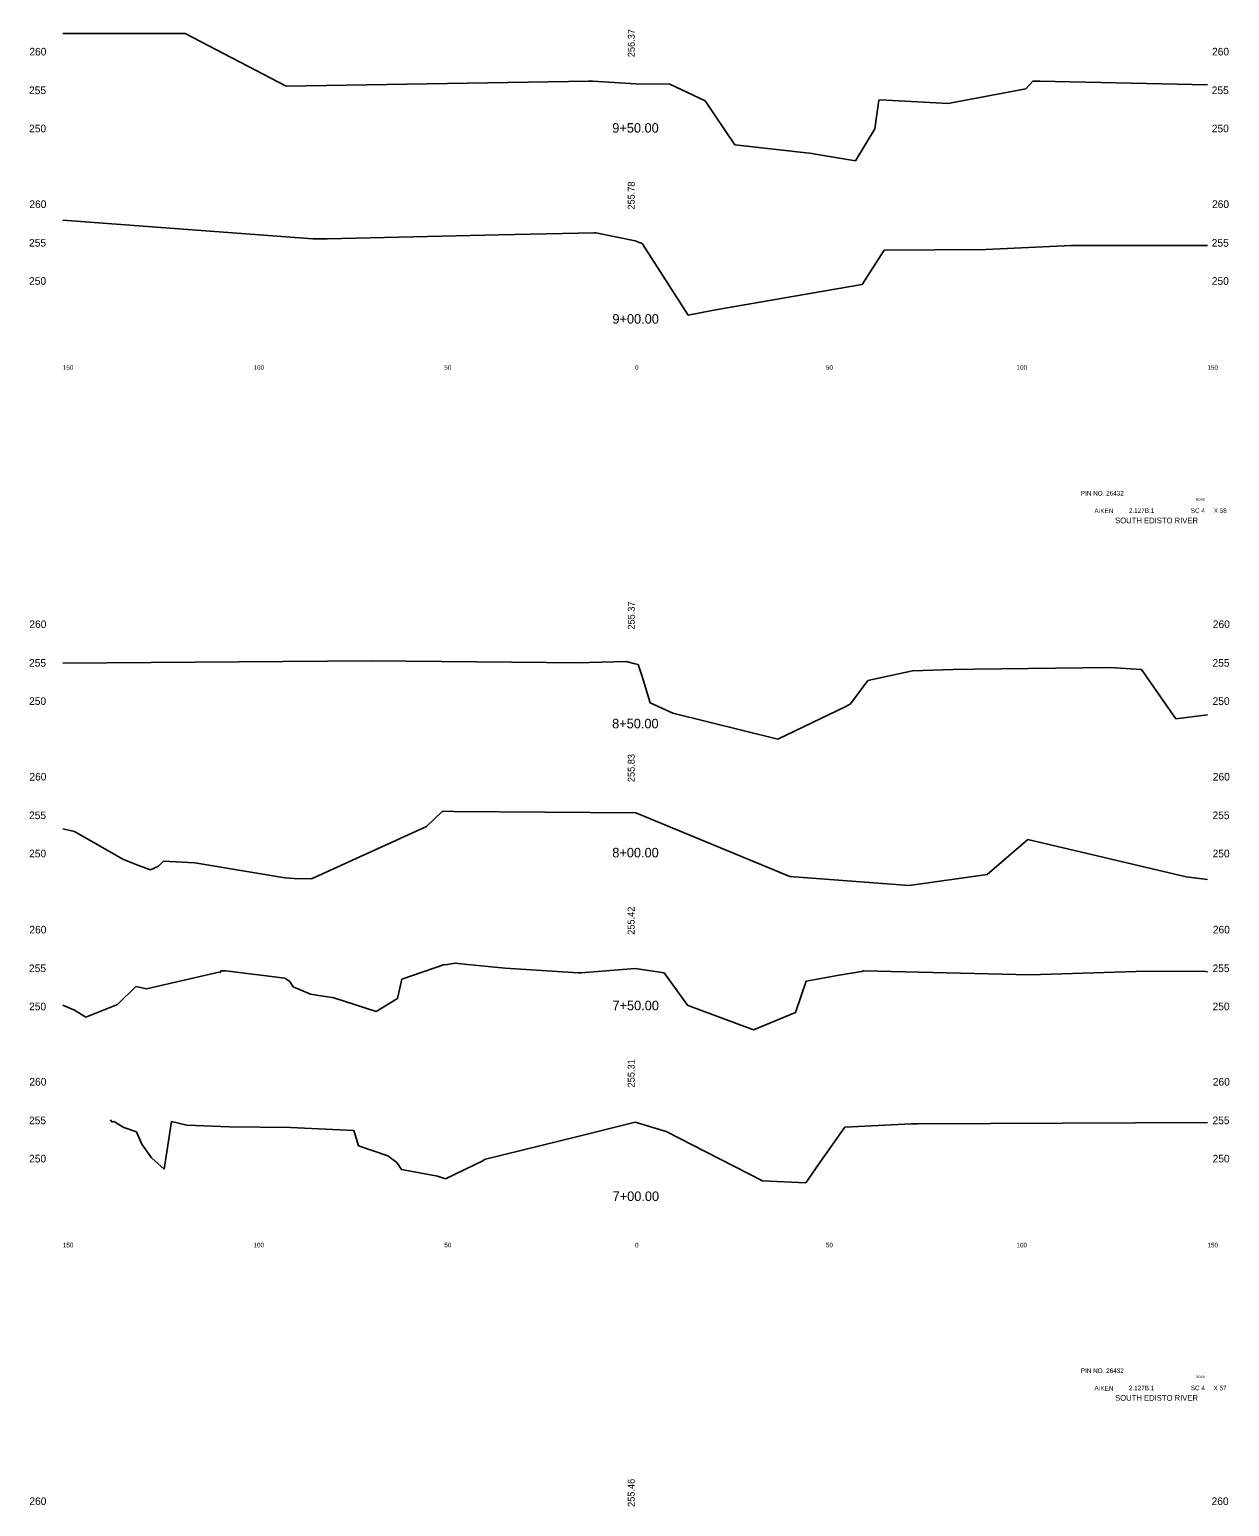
# Model space of a CAD drawing. Extents: x 557 to 872, y 628 to 2216.
# Drawn here: x 557.8 to 872.3, y 1029.9 to 1417 of the extents above; entities that cross this region are included whole.
import ezdxf

# ---------------------------------------------------------------- set-up
doc = ezdxf.new("R2010")
doc.units = 0
for name, color, linetype in [('Level 1', 7, 'Continuous'), ('Level 10', 7, 'Continuous'), ('Level 13', 7, 'Continuous'), ('Level 3', 7, 'Continuous'), ('Level 60', 7, 'Continuous')]:
    doc.layers.add(name, color=color, linetype=linetype)

msp = doc.modelspace()

# ---------------------------------------------------------------- linework, layer by layer
at = {"layer": 'Level 60'}
for p, q in [((566.54, 1415.97), (598.6, 1415.91)), ((598.6, 1415.91), (625.1, 1402.12)), ((625.1, 1402.12), (704.29, 1403.43)), ((704.29, 1403.43), (705.34, 1403.4)), ((705.34, 1403.4), (716.77, 1402.73)), ((716.77, 1402.73), (725.66, 1402.62)), ((725.66, 1402.62), (734.95, 1398.27)), ((799.45, 1397.77), (818.92, 1401.45)), ((818.92, 1401.45), (820.81, 1403.45)), ((820.81, 1403.45), (822.66, 1403.41)), ((822.66, 1403.41), (866.54, 1402.44)), ((734.95, 1398.27), (742.7, 1386.77)), ((779.37, 1390.94), (780.39, 1398.5)), ((780.39, 1398.5), (780.75, 1398.52)), ((780.75, 1398.52), (798.73, 1397.63)), ((798.73, 1397.63), (799.45, 1397.77)), ((774.32, 1382.57), (779.37, 1390.94)), ((742.7, 1386.77), (762.98, 1384.5)), ((762.98, 1384.5), (763.31, 1384.36)), ((763.31, 1384.36), (774.32, 1382.57)), ((566.54, 1367), (632.06, 1362.09)), ((635.92, 1362.11), (680.82, 1363.14)), ((680.82, 1363.14), (705.82, 1363.7)), ((705.82, 1363.7), (706.26, 1363.65)), ((706.26, 1363.65), (716.6, 1361.56)), ((632.06, 1362.09), (635.18, 1362.11)), ((635.18, 1362.11), (635.92, 1362.11)), ((716.6, 1361.56), (717.84, 1361.11)), ((717.84, 1361.11), (718.37, 1360.91)), ((718.37, 1360.91), (720.89, 1356.99)), ((776.09, 1350.16), (781.79, 1359.16)), ((781.79, 1359.16), (808.49, 1359.3)), ((808.49, 1359.3), (830.85, 1360.38)), ((830.85, 1360.38), (866.54, 1360.34)), ((720.89, 1356.99), (730.49, 1342.14)), ((751.76, 1345.98), (769.41, 1349.03)), ((769.41, 1349.03), (776.09, 1350.16)), ((730.49, 1342.14), (736.7, 1343.31)), ((736.7, 1343.31), (738.64, 1343.7)), ((738.64, 1343.7), (751.76, 1345.98)), ((566.54, 1250.94), (647.42, 1251.54)), ((647.42, 1251.54), (702.53, 1251.01)), ((702.53, 1251.01), (704.51, 1251.06)), ((704.51, 1251.06), (714.19, 1251.33)), ((714.19, 1251.33), (716.54, 1250.73)), ((716.54, 1250.73), (717.37, 1250.52)), ((717.37, 1250.52), (718.39, 1247.45)), ((718.39, 1247.45), (720.53, 1240.53)), ((777.56, 1246.39), (789.21, 1248.94)), ((789.21, 1248.94), (802.58, 1249.32)), ((802.58, 1249.32), (803.42, 1249.26)), ((803.42, 1249.26), (805.39, 1249.31)), ((805.39, 1249.31), (840.97, 1249.75)), ((840.97, 1249.75), (849.32, 1249.23)), ((849.32, 1249.23), (858.26, 1236.28)), ((772.97, 1240.24), (777.56, 1246.39)), ((720.53, 1240.53), (726.39, 1237.82)), ((753.96, 1230.95), (771.76, 1239.55)), ((771.76, 1239.55), (772.97, 1240.24)), ((726.39, 1237.82), (753.96, 1230.95)), ((858.26, 1236.28), (866.54, 1237.39)), ((661.87, 1208.06), (665.98, 1212.02)), ((665.98, 1212.02), (668.15, 1212.08)), ((668.15, 1212.08), (669.04, 1212.07)), ((669.04, 1212.07), (716.72, 1211.66)), ((716.72, 1211.66), (757.08, 1194.96)), ((631.71, 1194.37), (661.87, 1208.06)), ((566.54, 1207.49), (569.63, 1206.81)), ((569.63, 1206.81), (582.3, 1199.57)), ((808.84, 1195.54), (819.46, 1204.65)), ((819.46, 1204.65), (861.01, 1194.95)), ((582.3, 1199.57), (586.37, 1197.91)), ((586.37, 1197.91), (589.5, 1196.78)), ((589.5, 1196.78), (591.63, 1197.74)), ((591.63, 1197.74), (592.89, 1199.01)), ((592.89, 1199.01), (601.18, 1198.62)), ((601.18, 1198.62), (624.77, 1194.68)), ((624.77, 1194.68), (627.18, 1194.48)), ((627.18, 1194.48), (631.71, 1194.37)), ((757.08, 1194.96), (788.37, 1192.6)), ((788.37, 1192.6), (808.84, 1195.54)), ((861.01, 1194.95), (866.54, 1194.2)), ((588.5, 1165.51), (607.41, 1169.88)), ((607.41, 1169.88), (607.79, 1169.87)), ((607.79, 1169.87), (607.93, 1170.23)), ((607.93, 1170.23), (608.5, 1170.23)), ((608.5, 1170.23), (609.26, 1170.23)), ((609.26, 1170.23), (624.74, 1168.35)), ((655.37, 1168.08), (666.55, 1171.95)), ((666.55, 1171.95), (666.9, 1171.83)), ((666.9, 1171.83), (669.26, 1172.3)), ((669.26, 1172.3), (671.75, 1172)), ((671.75, 1172), (682.48, 1170.94)), ((682.48, 1170.94), (701.61, 1169.78)), ((701.61, 1169.78), (702.3, 1169.75)), ((702.3, 1169.75), (716.54, 1170.84)), ((716.54, 1170.84), (724.17, 1169.73)), ((724.17, 1169.73), (730.29, 1161.25)), ((761.42, 1167.59), (770.05, 1169.16)), ((770.05, 1169.16), (775.87, 1170.13)), ((775.87, 1170.13), (776.38, 1170.23)), ((776.38, 1170.23), (819.97, 1169.26)), ((819.97, 1169.26), (847.92, 1170.1)), ((847.92, 1170.1), (865.59, 1170.16)), ((865.59, 1170.16), (866.54, 1170.03)), ((580.91, 1161.49), (585.71, 1166.13)), ((585.71, 1166.13), (588.5, 1165.51)), ((624.74, 1168.35), (626.04, 1167.48)), ((626.04, 1167.48), (626.95, 1166.06)), ((626.95, 1166.06), (631.42, 1164.12)), ((654.25, 1162.99), (655.37, 1168.08)), ((758.59, 1159.39), (761.42, 1167.59)), ((566.54, 1161.31), (569.63, 1159.96)), ((572.6, 1158.11), (580.91, 1161.49)), ((631.42, 1164.12), (637.6, 1163.18)), ((637.6, 1163.18), (648.63, 1159.63)), ((648.63, 1159.63), (654.25, 1162.99)), ((569.63, 1159.96), (572.6, 1158.11)), ((730.29, 1161.25), (730.87, 1160.99)), ((730.87, 1160.99), (746.19, 1155.3)), ((747.61, 1154.84), (758.59, 1159.39)), ((746.19, 1155.3), (747.61, 1154.84)), ((579.07, 1131.21), (579.45, 1130.64)), ((579.45, 1130.64), (579.96, 1130.82)), ((579.96, 1130.82), (581.21, 1129.98)), ((593.07, 1118.31), (595.02, 1130.78)), ((595.02, 1130.78), (599.06, 1129.79)), ((701.88, 1126.96), (716.54, 1130.62)), ((716.54, 1130.62), (724.68, 1128.14)), ((790.75, 1130.21), (866.54, 1130.48)), ((581.21, 1129.98), (582.57, 1129.17)), ((582.57, 1129.17), (585.82, 1128.09)), ((585.82, 1128.09), (587.21, 1124.87)), ((599.06, 1129.79), (610.2, 1129.36)), ((610.2, 1129.36), (626.26, 1129.23)), ((626.26, 1129.23), (642.82, 1128.38)), ((642.82, 1128.38), (644.05, 1124.37)), ((676.96, 1120.78), (701.88, 1126.96)), ((724.68, 1128.14), (735.1, 1122.79)), ((765.37, 1120.61), (771.53, 1129.32)), ((771.53, 1129.32), (788.97, 1130.18)), ((788.97, 1130.18), (789.95, 1130.18)), ((789.95, 1130.18), (790.75, 1130.21)), ((587.21, 1124.87), (589.78, 1121.27)), ((644.05, 1124.37), (651.69, 1121.76)), ((735.1, 1122.79), (749.9, 1115.2)), ((589.78, 1121.27), (593.07, 1118.31)), ((651.69, 1121.76), (654.13, 1120.04)), ((654.13, 1120.04), (655.34, 1118.16)), ((666.82, 1115.79), (676.81, 1120.59)), ((676.81, 1120.59), (676.96, 1120.78)), ((761.31, 1114.71), (765.37, 1120.61)), ((655.34, 1118.16), (664.73, 1116.46)), ((664.73, 1116.46), (666.82, 1115.79)), ((749.9, 1115.2), (761.31, 1114.71))]:
    msp.add_line(p, q, dxfattribs=at)

# ---------------------------------------------------------------- texts
at = {"layer": 'Level 1'}
for s, height, p in [('9+50.00', 2.5, (710.56, 1389.94)), ('9+00.00', 2.5, (710.6, 1339.89)), ('PIN NO. 26432', 1.2, (833.38, 1294.84)), ('ROAD', 0.6, (863.53, 1293.51)), ('AIKEN', 1.2, (836.93, 1290.24)), ('SOUTH EDISTO RIVER', 1.5, (842.36, 1287.55)), (' 2.127B.1', 1.2, (845.53, 1290.29)), ('SC 4', 1.2, (862.2, 1290.31)), ('X 58', 1.2, (868.23, 1290.31)), ('8+50.00', 2.5, (710.52, 1233.83)), ('8+00.00', 2.5, (710.56, 1200)), ('7+50.00', 2.5, (710.61, 1159.94)), ('7+00.00', 2.5, (710.65, 1109.95)), ('PIN NO. 26432', 1.2, (833.38, 1064.88)), ('AIKEN', 1.2, (836.93, 1060.28)), (' 2.127B.1', 1.2, (845.53, 1060.33)), ('SC 4', 1.2, (862.2, 1060.35)), ('ROAD', 0.6, (863.53, 1063.54)), ('X 57', 1.2, (868.15, 1060.32)), ('SOUTH EDISTO RIVER', 1.5, (842.36, 1057.59))]:
    msp.add_text(s, height=height, dxfattribs=at).set_placement(p)
at = {"layer": 'Level 10'}
for s, p in [('256.37', (716.44, 1409.73)), ('255.78', (716.43, 1369.78)), ('255.37', (716.44, 1259.71)), ('255.83', (716.43, 1219.73)), ('255.42', (716.4, 1179.72)), ('255.31', (716.42, 1139.72)), ('255.46', (716.43, 1029.77))]:
    msp.add_text(s, height=1.8, rotation=90, dxfattribs=at).set_placement(p)
at = {"layer": 'Level 13'}
for s, p in [('150', (566.54, 1327.8)), ('100', (616.54, 1327.8)), ('50', (666.54, 1327.8)), ('0', (716.54, 1327.8)), ('50', (766.54, 1327.8)), ('100', (816.54, 1327.8)), ('150', (866.54, 1327.8)), ('150', (566.54, 1097.8)), ('100', (616.54, 1097.8)), ('50', (666.54, 1097.8)), ('0', (716.54, 1097.8)), ('50', (766.54, 1097.8)), ('100', (816.54, 1097.8)), ('150', (866.54, 1097.8))]:
    msp.add_text(s, height=1.2, dxfattribs=at).set_placement(p)
at = {"layer": 'Level 3'}
for s, p in [(' 260', (557.03, 1410.18)), (' 260', (867.02, 1410.18)), (' 255', (556.94, 1400.05)), (' 255', (866.94, 1400.05)), (' 250', (556.96, 1390.04)), (' 250', (866.96, 1390.04)), (' 260', (557.03, 1370.2)), (' 260', (867.02, 1370.2)), (' 255', (556.94, 1360.08)), (' 255', (866.94, 1360.08)), (' 250', (556.96, 1350.07)), (' 250', (866.96, 1350.07)), (' 260', (557.03, 1260.11)), (' 260', (867.23, 1260.11)), (' 255', (556.94, 1249.98)), (' 255', (867.15, 1249.98)), (' 250', (556.96, 1239.97)), (' 250', (867.17, 1239.97)), (' 260', (557.03, 1220.15)), (' 260', (867.23, 1220.15)), (' 255', (556.94, 1210.03)), (' 255', (867.15, 1210.03)), (' 250', (556.96, 1200.02)), (' 250', (867.17, 1200.02)), (' 260', (557.03, 1180.07)), (' 260', (867.23, 1180.07)), (' 255', (556.94, 1169.94)), (' 255', (867.15, 1169.94)), (' 250', (556.96, 1159.93)), (' 250', (867.17, 1159.93)), (' 260', (557.03, 1140.19)), (' 260', (867.23, 1140.19)), (' 255', (556.94, 1130.07)), (' 255', (867.15, 1130.07)), (' 250', (556.96, 1120.05)), (' 250', (867.17, 1120.05)), (' 260', (557.03, 1030.26)), (' 260', (866.9, 1030.26))]:
    msp.add_text(s, height=2, dxfattribs=at).set_placement(p)

doc.saveas('drawing.dxf')
